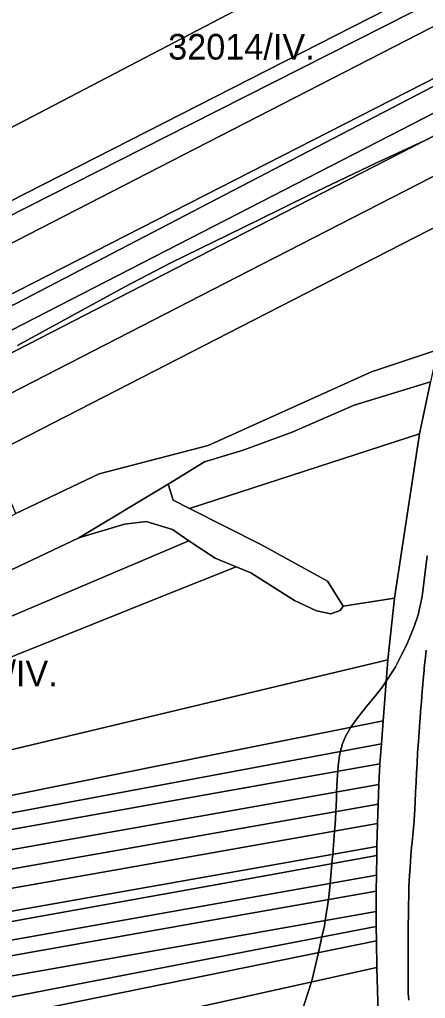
# Model space of a CAD drawing. Extents: x -521939 to -516426, y -1197857 to -1189551.
# Drawn here: x -521063 to -520825, y -1190786 to -1190213 of the extents above; entities that cross this region are included whole.
import ezdxf

# ---------------------------------------------------------------- set-up
doc = ezdxf.new("R2010")
doc.units = 0
for name, color, linetype in [('95560013', 7, 'Continuous'), ('95610013', 7, 'Continuous'), ('95640013', 7, 'Continuous'), ('95660013', 7, 'Continuous')]:
    doc.layers.add(name, color=color, linetype=linetype)

msp = doc.modelspace()

# ---------------------------------------------------------------- linework, layer by layer
at = {"layer": '95560013'}
msp.add_lwpolyline([(-520777.95, -1190124.57), (-521143.74, -1190315.4), (-521187.47, -1190337.7), (-521350.33, -1190420.75), (-521513.19, -1190503.8), (-521509.92, -1190475.58), (-521501.05, -1190385.07), (-521492.81, -1190317.35), (-521482.93, -1190243.69), (-521480.04, -1190222.68), (-521467.81, -1190165.95)], dxfattribs=at)
for points in [[(-521143.74, -1190315.4), (-520777.95, -1190124.57), (-520777.29, -1190138.74), (-520776.47, -1190163.36), (-520776.83, -1190170.44), (-521129.32, -1190350.03), (-521136.18, -1190333.63), (-521138.91, -1190327.09), (-521141.12, -1190321.7)], [(-521125.92, -1190356.73), (-521201.05, -1190394.9), (-521360.62, -1190475.97), (-521520.19, -1190557.04), (-521519.05, -1190548.23), (-521358.95, -1190466.81), (-521197.1, -1190384.5), (-521129.32, -1190350.03), (-520776.83, -1190170.44), (-520777.49, -1190180.07), (-520800.29, -1190191.63), (-520962.75, -1190274)], [(-521125.92, -1190356.73), (-520962.75, -1190274), (-520800.29, -1190191.63), (-520777.49, -1190180.07), (-520778.53, -1190195.44), (-520799.56, -1190206.22), (-520959.86, -1190288.39), (-521120.16, -1190370.56), (-521122.27, -1190365.51)], [(-521120.16, -1190370.56), (-520959.86, -1190288.39), (-520799.56, -1190206.22), (-520778.53, -1190195.44), (-520780.79, -1190226.94), (-520945.61, -1190311.1), (-521109.96, -1190395.02), (-521115.96, -1190380.58)], [(-520780.79, -1190226.94), (-520781.3, -1190231.43), (-520947.47, -1190317.86), (-521107.43, -1190401.06), (-521220.55, -1190459.05), (-521223.37, -1190452.93), (-521109.96, -1190395.02), (-520945.61, -1190311.1)], [(-521107.43, -1190401.06), (-520947.47, -1190317.86), (-520781.3, -1190231.43), (-520784.36, -1190249.11), (-520942.18, -1190330.09), (-521102.67, -1190412.44), (-521105.13, -1190406.56)], [(-521102.67, -1190412.44), (-520942.18, -1190330.09), (-520784.36, -1190249.11), (-520786.83, -1190263.81), (-520937.98, -1190341.34), (-521098.02, -1190423.43), (-521100.33, -1190417.95)], [(-521098.02, -1190423.43), (-520937.98, -1190341.34), (-520786.83, -1190263.81), (-520791.44, -1190289.68), (-520928.2, -1190359.84), (-521089.93, -1190442.81), (-521093.32, -1190434.69)], [(-520799.14, -1190323.82), (-520918.15, -1190384.84), (-521079.58, -1190467.61), (-521082.1, -1190461.56), (-521086.88, -1190450.16), (-521089.93, -1190442.81), (-520928.2, -1190359.84), (-520791.44, -1190289.68)], [(-521079.58, -1190467.61), (-520918.15, -1190384.84), (-520799.14, -1190323.82), (-520803.11, -1190340.79), (-520817.75, -1190406.02), (-520856.45, -1190418.91), (-520952.31, -1190462.12), (-521016.12, -1190478.68), (-521065.06, -1190501.97), (-521071.49, -1190486.71), (-521074.5, -1190479.57), (-521077.03, -1190473.61)], [(-520975.71, -1190484.83), (-520954.38, -1190471.58), (-520931.67, -1190464.89), (-520903.05, -1190454.36), (-520866.64, -1190438.5), (-520822, -1190424.77), (-520828.37, -1190455.3), (-520963.26, -1190499.05), (-520972.83, -1190494.21)], [(-520828.37, -1190455.3), (-520842.97, -1190551.61), (-520873.05, -1190556.16), (-520882.3, -1190541.54), (-520920.98, -1190520.29), (-520963.26, -1190499.05)], [(-521579.75, -1190768.48), (-521547.67, -1190758.86), (-521384.14, -1190686.63), (-521226.27, -1190616.9), (-521208.81, -1190607.77), (-521117.2, -1190558.41), (-521028.03, -1190516.13), (-521001.35, -1190508.14), (-520988.56, -1190506.62), (-520973.08, -1190511.3), (-520963.57, -1190517.89), (-521091.14, -1190572.1), (-521258.08, -1190643.04), (-521425.02, -1190713.98), (-521591.96, -1190784.92)], [(-521591.96, -1190784.92), (-521425.02, -1190713.98), (-521258.08, -1190643.04), (-521091.14, -1190572.1), (-520963.57, -1190517.89), (-520948.08, -1190528.14), (-520935.85, -1190533.17), (-520975.03, -1190548.84), (-521132.5, -1190611.82), (-521290.17, -1190674.88), (-521437.14, -1190733.56), (-521603.17, -1190799.85)], [(-520873.05, -1190556.16), (-520842.97, -1190551.61), (-520846.95, -1190587.68), (-520947.61, -1190611.64), (-521120.53, -1190652.8), (-521293.24, -1190693.91), (-521290.17, -1190674.88), (-521132.5, -1190611.82), (-520975.03, -1190548.84), (-520935.85, -1190533.17), (-520927.18, -1190536.7), (-520901.63, -1190552.85), (-520888.76, -1190558.89), (-520880.26, -1190560.73), (-520874.86, -1190558.72)], [(-521296.33, -1190712.88), (-521293.24, -1190693.91), (-521120.53, -1190652.8), (-520947.61, -1190611.64), (-520846.95, -1190587.68), (-520849.58, -1190623.3), (-520946.68, -1190642.77), (-521121.53, -1190677.83)], [(-521297.51, -1190719.97), (-521296.33, -1190712.88), (-521121.53, -1190677.83), (-520946.68, -1190642.77), (-520849.58, -1190623.3), (-520850.63, -1190636.95), (-520939.5, -1190653.46), (-521119.77, -1190686.95)], [(-521298.87, -1190728.16), (-521297.51, -1190719.97), (-521119.77, -1190686.95), (-520939.5, -1190653.46), (-520850.63, -1190636.95), (-520851.64, -1190648.56), (-520948.39, -1190665.78), (-521123.63, -1190696.97)], [(-521300.83, -1190740.08), (-521298.87, -1190728.16), (-521123.63, -1190696.97), (-520948.39, -1190665.78), (-520851.64, -1190648.56), (-520852.28, -1190660.73), (-520950.13, -1190678.04), (-521125.48, -1190709.06)], [(-521302.74, -1190751.74), (-521300.83, -1190740.08), (-521125.48, -1190709.06), (-520950.13, -1190678.04), (-520852.28, -1190660.73), (-520852.56, -1190672.24), (-520946.39, -1190688.81), (-521124.48, -1190720.26)], [(-521304.64, -1190763.28), (-521302.74, -1190751.74), (-521124.48, -1190720.26), (-520946.39, -1190688.81), (-520852.56, -1190672.24), (-520852.94, -1190683.51), (-520953.28, -1190701.23), (-521131.31, -1190732.67)], [(-521306.54, -1190774.85), (-521304.64, -1190763.28), (-521131.31, -1190732.67), (-520953.28, -1190701.23), (-520852.94, -1190683.51), (-520853.37, -1190697.08), (-520944.6, -1190713.16), (-521121.67, -1190744.37), (-521306.91, -1190777.02)], [(-521308.13, -1190784.21), (-521129.72, -1190752.09), (-520951.31, -1190719.97), (-520853.44, -1190702.35), (-520853.63, -1190713.88), (-520965.54, -1190733.72), (-521143.84, -1190765.33), (-521309.9, -1190794.77), (-521308.62, -1190787.06)], [(-521306.91, -1190777.02), (-521121.67, -1190744.37), (-520944.6, -1190713.16), (-520853.37, -1190697.08), (-520853.44, -1190702.35), (-520951.31, -1190719.97), (-521129.72, -1190752.09), (-521308.13, -1190784.21)], [(-521310.55, -1190798.66), (-521309.9, -1190794.77), (-521143.84, -1190765.33), (-520965.54, -1190733.72), (-520853.63, -1190713.88), (-520853.79, -1190723.11), (-520956.84, -1190741.35), (-521130.85, -1190772.15), (-521311.47, -1190804.12)], [(-520853.79, -1190723.11), (-520853.87, -1190735.1), (-520958.48, -1190753.58), (-521136, -1190784.94), (-521313.52, -1190816.3), (-521311.47, -1190804.12), (-521130.85, -1190772.15), (-520956.84, -1190741.35)], [(-521313.52, -1190816.3), (-521136, -1190784.94), (-520958.48, -1190753.58), (-520853.87, -1190735.1), (-520853.81, -1190743.83), (-520959.05, -1190764.12), (-521138.15, -1190798.65), (-521317.25, -1190833.18), (-521501.29, -1190868.66), (-521677.29, -1190902.59), (-521660.16, -1190877.52), (-521482.65, -1190846.17)], [(-521681.39, -1190911.18), (-521677.29, -1190902.59), (-521501.29, -1190868.66), (-521317.25, -1190833.18), (-521138.15, -1190798.65), (-520959.05, -1190764.12), (-520853.81, -1190743.83), (-520853.6, -1190752.22), (-520963.96, -1190774.66), (-521145.09, -1190811.49), (-521320.22, -1190847.1), (-521372.85, -1190856.47), (-521425.01, -1190865.8), (-521453.93, -1190870.89), (-521460.01, -1190871.96), (-521483.31, -1190876.02), (-521504.24, -1190879.82), (-521526.13, -1190883.61), (-521548.65, -1190887.54)], [(-520853.6, -1190752.22), (-520853.48, -1190767.88), (-520962.56, -1190792.05), (-521140.87, -1190831.56), (-521319.18, -1190871.07), (-521320.22, -1190847.1), (-521145.09, -1190811.49), (-520963.96, -1190774.66)]]:
    msp.add_lwpolyline(points, close=True, dxfattribs=at)
at = {"layer": '95610013'}
msp.add_lwpolyline([(-520853.48, -1190767.88), (-520852.66, -1190794.34), (-520930.46, -1190808.82), (-521026.22, -1190830.89), (-521057.89, -1190837.57), (-521100.8, -1190846.62), (-521144.36, -1190855.59), (-521318.26, -1190891.4), (-521319.18, -1190871.07), (-521140.87, -1190831.56), (-520962.56, -1190792.05)], close=True, dxfattribs=at)
at = {"layer": '95640013'}
for points in [[(-521510.56, -1190730.26), (-521346.43, -1190657.14), (-521249.64, -1190614.02), (-521203.97, -1190579.5), (-521065.06, -1190501.97), (-521016.12, -1190478.68), (-520952.31, -1190462.12), (-520856.45, -1190418.91), (-520817.75, -1190406.02), (-520822, -1190424.77), (-520866.64, -1190438.5), (-520903.05, -1190454.36), (-520931.67, -1190464.89), (-520954.38, -1190471.58), (-520975.71, -1190484.83), (-521028.03, -1190516.13), (-521117.2, -1190558.41), (-521208.81, -1190607.77), (-521226.27, -1190616.9), (-521384.14, -1190686.63), (-521547.67, -1190758.86), (-521579.75, -1190768.48), (-521566.68, -1190750.61), (-521543.77, -1190745.06)], [(-520963.26, -1190499.05), (-520920.98, -1190520.29), (-520882.3, -1190541.54), (-520873.05, -1190556.16), (-520874.86, -1190558.72), (-520880.26, -1190560.73), (-520888.76, -1190558.89), (-520901.63, -1190552.85), (-520927.18, -1190536.7), (-520935.85, -1190533.17), (-520948.08, -1190528.14), (-520963.57, -1190517.89), (-520973.08, -1190511.3), (-520988.56, -1190506.62), (-521001.35, -1190508.14), (-521028.03, -1190516.13), (-520975.71, -1190484.83), (-520972.83, -1190494.21)]]:
    msp.add_lwpolyline(points, close=True, dxfattribs=at)
for points in [[(-520852.66, -1190794.34), (-520853.48, -1190767.88), (-520853.6, -1190752.22), (-520853.81, -1190743.83), (-520853.87, -1190735.1), (-520853.79, -1190723.11), (-520853.63, -1190713.88), (-520853.44, -1190702.35), (-520853.37, -1190697.08), (-520852.94, -1190683.51), (-520852.56, -1190672.24), (-520852.28, -1190660.73), (-520851.64, -1190648.56), (-520850.63, -1190636.95), (-520849.58, -1190623.3), (-520846.95, -1190587.68), (-520842.97, -1190551.61), (-520828.37, -1190455.3), (-520822, -1190424.77)], [(-520834.61, -1190787.07), (-520834.92, -1190782.92), (-520834.94, -1190780.45), (-520834.99, -1190774.65), (-520835.04, -1190768.27), (-520835.08, -1190762.76), (-520835.08, -1190762.45), (-520835.08, -1190762.16), (-520835.05, -1190756.12), (-520835.02, -1190749.26), (-520834.99, -1190743.76), (-520834.99, -1190742.61), (-520834.91, -1190737.42), (-520834.82, -1190731.68), (-520834.72, -1190725.53), (-520834.67, -1190722.46), (-520834.57, -1190720.65), (-520834.19, -1190713.84), (-520833.93, -1190709.32), (-520833.53, -1190702.3), (-520833.06, -1190697.52), (-520832.56, -1190692.51), (-520831.92, -1190686.11), (-520831.53, -1190682.22), (-520831.48, -1190681.4), (-520831.18, -1190675.42), (-520830.95, -1190670.95), (-520830.65, -1190664.99), (-520830.5, -1190662.17), (-520830.37, -1190659.51), (-520830.09, -1190653.98), (-520829.81, -1190648.4), (-520829.5, -1190642.29), (-520829.49, -1190642.08), (-520829, -1190635.46), (-520828.79, -1190632.68), (-520828.59, -1190629.93), (-520828.13, -1190623.75), (-520828, -1190622.02), (-520827.69, -1190617.85), (-520827.28, -1190612.32), (-520826.82, -1190606.09), (-520826.51, -1190601.96), (-520826.28, -1190599.56), (-520825.69, -1190593.61), (-520825.59, -1190592.55), (-520825.25, -1190589.08), (-520825.13, -1190587.77), (-520824.56, -1190581.94)], [(-520824.56, -1190581.94), (-520825.13, -1190587.77), (-520825.25, -1190589.08), (-520825.59, -1190592.55), (-520825.69, -1190593.61), (-520826.28, -1190599.56), (-520826.51, -1190601.96), (-520826.82, -1190606.09), (-520827.28, -1190612.32), (-520827.69, -1190617.85), (-520828, -1190622.02), (-520828.13, -1190623.75), (-520828.59, -1190629.93), (-520828.79, -1190632.68), (-520829, -1190635.46), (-520829.49, -1190642.08), (-520829.5, -1190642.29), (-520829.81, -1190648.4), (-520830.09, -1190653.98), (-520830.37, -1190659.51), (-520830.5, -1190662.17), (-520830.65, -1190664.99), (-520830.95, -1190670.95), (-520831.18, -1190675.42), (-520831.48, -1190681.4), (-520831.53, -1190682.22), (-520831.92, -1190686.11), (-520832.56, -1190692.51), (-520833.06, -1190697.52), (-520833.53, -1190702.3), (-520833.93, -1190709.32), (-520834.19, -1190713.84), (-520834.57, -1190720.65), (-520834.67, -1190722.46), (-520834.72, -1190725.53), (-520834.82, -1190731.68), (-520834.91, -1190737.42), (-520834.99, -1190742.61), (-520834.99, -1190743.76), (-520835.02, -1190749.26), (-520835.05, -1190756.12), (-520835.08, -1190762.16), (-520835.08, -1190762.45), (-520835.08, -1190762.76), (-520835.04, -1190768.27), (-520834.99, -1190774.65), (-520834.94, -1190780.45), (-520834.92, -1190782.92), (-520834.61, -1190787.07)]]:
    msp.add_lwpolyline(points, dxfattribs=at)
at = {"layer": '95660013'}
for points in [[(-521064.04, -1190403.6), (-521001.12, -1190369.09), (-520974.6, -1190355.36), (-520922.48, -1190330.01), (-520892.91, -1190315.34), (-520854.06, -1190296.67), (-520822.77, -1190282.24)], [(-520822.77, -1190282.24), (-520854.06, -1190296.67), (-520892.91, -1190315.34), (-520922.48, -1190330.01), (-520974.6, -1190355.36), (-521001.12, -1190369.09), (-521064.04, -1190403.6)], [(-520899.83, -1190801.72), (-520891.7, -1190776.35), (-520891.49, -1190775.69), (-520887.67, -1190759.15), (-520885.55, -1190749.95), (-520884.06, -1190743.5), (-520883.6, -1190740.35), (-520881.79, -1190728.07), (-520881.29, -1190724.69), (-520880.75, -1190718.69), (-520879.69, -1190707.08), (-520879.67, -1190706.84), (-520879.24, -1190701.64), (-520878.11, -1190687.95), (-520877.81, -1190684.35), (-520877.46, -1190676.64), (-520877.12, -1190669.28), (-520876.95, -1190665.09), (-520876.66, -1190657.92), (-520876.23, -1190652.94), (-520876.22, -1190652.87), (-520875.96, -1190649.81), (-520875.26, -1190643.78), (-520874.67, -1190641.42), (-520873.64, -1190637.29), (-520871.79, -1190632.65), (-520868.54, -1190627.09), (-520864.6, -1190621.52), (-520858.57, -1190614.11), (-520854.65, -1190609.23), (-520850, -1190603.44), (-520847.87, -1190600.18), (-520842.58, -1190592.08), (-520839.89, -1190586.7), (-520835.85, -1190578.64), (-520831.45, -1190568.21), (-520829.13, -1190561.25), (-520826.81, -1190550.59), (-520825.42, -1190539.46), (-520823.92, -1190526.67)], [(-520823.92, -1190526.67), (-520825.42, -1190539.46), (-520826.81, -1190550.59), (-520829.13, -1190561.25), (-520831.45, -1190568.21), (-520835.85, -1190578.64), (-520839.89, -1190586.7), (-520842.58, -1190592.08), (-520847.87, -1190600.18), (-520850, -1190603.44), (-520854.65, -1190609.23), (-520858.57, -1190614.11), (-520864.6, -1190621.52), (-520868.54, -1190627.09), (-520871.79, -1190632.65), (-520873.64, -1190637.29), (-520874.67, -1190641.42), (-520875.26, -1190643.78), (-520875.96, -1190649.81), (-520876.22, -1190652.87), (-520876.23, -1190652.94), (-520876.66, -1190657.92), (-520876.95, -1190665.09), (-520877.12, -1190669.28), (-520877.46, -1190676.64), (-520877.81, -1190684.35), (-520878.11, -1190687.95), (-520879.24, -1190701.64), (-520879.67, -1190706.84), (-520879.69, -1190707.08), (-520880.75, -1190718.69), (-520881.29, -1190724.69), (-520881.79, -1190728.07), (-520883.6, -1190740.35), (-520884.06, -1190743.5), (-520885.55, -1190749.95), (-520887.67, -1190759.15), (-520891.49, -1190775.69), (-520891.7, -1190776.35), (-520899.83, -1190801.72)]]:
    msp.add_lwpolyline(points, dxfattribs=at)

# ---------------------------------------------------------------- texts
for s, rotation, p in [('32014/IV.', 360, (-520975.7, -1190236.05)), ('32011/IV.', 0, (-521126.31, -1190603.09))]:
    msp.add_text(s, height=15, rotation=rotation, dxfattribs=at).set_placement(p)

doc.saveas('drawing.dxf')
